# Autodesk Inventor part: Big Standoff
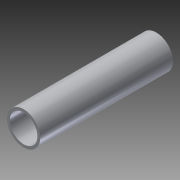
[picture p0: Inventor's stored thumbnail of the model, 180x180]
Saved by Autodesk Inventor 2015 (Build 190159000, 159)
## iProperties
Created: 2014-08
Part Number: Big Standoff
Material: Aluminum 6061
Document SubType Name: Modeling
Designer: User
Density: 2.71 g/cm^3
Appearance: Aluminum - Flat
Author: User
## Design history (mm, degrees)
sketch "Sketch1"
  geometry: C1 r 9.525 at (0, 0); C2 r 7.938 at (0, 0); 1 further point
  constraints: 2 centre point, 2 coincident
  dimensions: "d0" = 19.05 diameter of C1; "d1" = 15.875 diameter of C2
extrude "Extrusion1" new body sketch "Sketch1" distance "d2" = 76.2; taper "d3" = 0 deg
body "Solid1"
